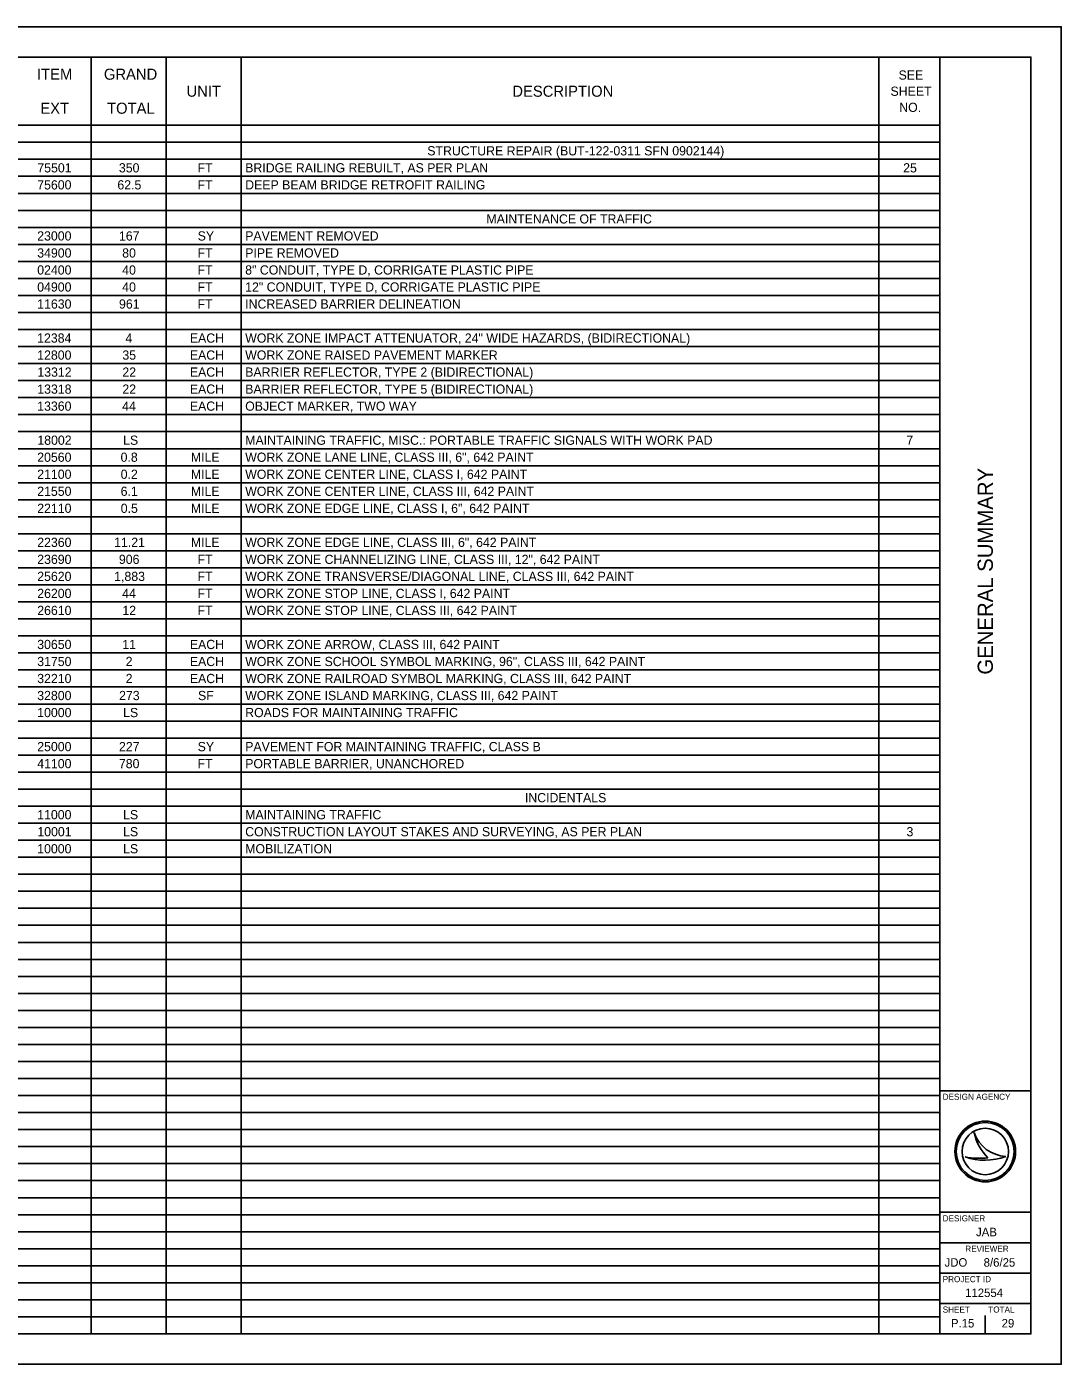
# Model space of a CAD drawing. Extents: x 45.7 to 120.9, y -0.1 to 21.9.
# Drawn here: x 103.83 to 120.86, y -0.09 to 21.91 of the extents above; entities that cross this region are included whole.
import ezdxf

# ---------------------------------------------------------------- set-up
doc = ezdxf.new("R2010")
doc.units = 0
for name, color, linetype in [('SH_Border', 7, 'Continuous'), ('SH_Cut_Line', 7, 'Continuous'), ('SH_Data', 7, 'Continuous'), ('SH_Text', 7, 'Continuous')]:
    doc.layers.add(name, color=color, linetype=linetype)

msp = doc.modelspace()

# ---------------------------------------------------------------- linework, layer by layer
at = {"layer": 'SH_Border'}
for p, q in [((118.856, 0.409), (118.856, 21.409)), ((118.856, 4.409), (120.356, 4.409)), ((118.856, 2.409), (120.356, 2.409)), ((118.856, 1.909), (120.356, 1.909)), ((118.856, 1.409), (120.356, 1.409)), ((118.856, 0.909), (120.356, 0.909))]:
    msp.add_line(p, q, dxfattribs=at)
msp.add_lwpolyline([(88.356, 21.409), (120.356, 21.409), (120.356, 0.409), (88.356, 0.409)], close=True, dxfattribs=at)
at = {"layer": 'SH_Cut_Line'}
msp.add_lwpolyline([(86.856, -0.091), (120.856, -0.091), (120.856, 21.909), (86.856, 21.909)], close=True, dxfattribs=at)
at = {"layer": 'SH_Data'}
for p, q in [((119.424, 3.719), (119.424, 3.719)), ((119.274, 3.319), (119.274, 3.319)), ((119.606, 3.409), (119.606, 3.409)), ((119.944, 3.328), (119.944, 3.328)), ((119.606, 0.409), (119.606, 0.709)), ((119.231, 0.584), (119.231, 0.584))]:
    msp.add_line(p, q, dxfattribs=at)
for radius in [0.5, 0.477, 0.477, 0.382]:
    msp.add_circle((119.606, 3.409), radius, dxfattribs=at)
for centre, radius, start, end in [((119.972, 3.907), 0.58, 198.9257, 198.9319), ((120.203, 3.879), 0.796, 191.6379, 191.6421), ((119.972, 3.907), 0.58, 198.9319, 267.1657), ((120.203, 3.879), 0.796, 191.6421, 226.0947), ((119.596, 4.279), 1.013, 251.4576, 290.0832), ((119.504, 4.563), 1.266, 259.4964, 259.4995), ((119.596, 4.279), 1.013, 251.4527, 251.4576), ((119.504, 4.563), 1.266, 259.4995, 276.6672)]:
    msp.add_arc(centre, radius, start, end, dxfattribs=at)
at = {"layer": 'SH_Text'}
for p, q in [((88.356, 21.409), (118.86, 21.409)), ((104.893, 21.409), (104.893, 0.409)), ((106.128, 21.409), (106.128, 0.409)), ((107.363, 21.409), (107.363, 0.409)), ((117.855, 21.409), (117.855, 0.409)), ((118.86, 21.409), (118.86, 0.409)), ((88.356, 20.289), (118.86, 20.289)), ((88.356, 20.009), (118.86, 20.009)), ((88.356, 19.729), (118.86, 19.729)), ((88.356, 19.449), (118.86, 19.449)), ((88.356, 19.169), (118.86, 19.169)), ((88.356, 18.889), (118.86, 18.889)), ((88.356, 18.609), (118.86, 18.609)), ((88.356, 18.329), (118.86, 18.329)), ((88.356, 18.049), (118.86, 18.049)), ((88.356, 17.769), (118.86, 17.769)), ((88.356, 17.489), (118.86, 17.489)), ((88.356, 17.209), (118.86, 17.209)), ((88.356, 16.929), (118.86, 16.929)), ((88.356, 16.649), (118.86, 16.649)), ((88.356, 16.369), (118.86, 16.369)), ((88.356, 16.089), (118.86, 16.089)), ((88.356, 15.809), (118.86, 15.809)), ((88.356, 15.529), (118.86, 15.529)), ((88.356, 15.249), (118.86, 15.249)), ((88.356, 14.969), (118.86, 14.969)), ((88.356, 14.689), (118.86, 14.689)), ((88.356, 14.409), (118.86, 14.409)), ((88.356, 14.129), (118.86, 14.129)), ((88.356, 13.849), (118.86, 13.849)), ((88.356, 13.569), (118.86, 13.569)), ((88.356, 13.289), (118.86, 13.289)), ((88.356, 13.009), (118.86, 13.009)), ((88.356, 12.729), (118.86, 12.729)), ((88.356, 12.449), (118.86, 12.449)), ((88.356, 12.169), (118.86, 12.169)), ((88.356, 11.889), (118.86, 11.889)), ((88.356, 11.609), (118.86, 11.609)), ((88.356, 11.329), (118.86, 11.329)), ((88.356, 11.049), (118.86, 11.049)), ((88.356, 10.769), (118.86, 10.769)), ((88.356, 10.489), (118.86, 10.489)), ((88.356, 10.209), (118.86, 10.209)), ((88.356, 9.929), (118.86, 9.929)), ((88.356, 9.649), (118.86, 9.649)), ((88.356, 9.369), (118.86, 9.369)), ((88.356, 9.089), (118.86, 9.089)), ((88.356, 8.809), (118.86, 8.809)), ((88.356, 8.529), (118.86, 8.529)), ((88.356, 8.249), (118.86, 8.249)), ((88.356, 7.969), (118.86, 7.969)), ((88.356, 7.689), (118.86, 7.689)), ((88.356, 7.409), (118.86, 7.409)), ((88.356, 7.129), (118.86, 7.129)), ((88.356, 6.849), (118.86, 6.849)), ((88.356, 6.569), (118.86, 6.569)), ((88.356, 6.289), (118.86, 6.289)), ((88.356, 6.009), (118.86, 6.009)), ((88.356, 5.729), (118.86, 5.729)), ((88.356, 5.449), (118.86, 5.449)), ((88.356, 5.169), (118.86, 5.169)), ((88.356, 4.889), (118.86, 4.889)), ((88.356, 4.609), (118.86, 4.609)), ((88.356, 4.329), (118.86, 4.329)), ((88.356, 4.049), (118.86, 4.049)), ((88.356, 3.769), (118.86, 3.769)), ((88.356, 3.489), (118.86, 3.489)), ((88.356, 3.209), (118.86, 3.209)), ((88.356, 2.929), (118.86, 2.929)), ((88.356, 2.649), (118.86, 2.649)), ((88.356, 2.369), (118.86, 2.369)), ((88.356, 2.089), (118.86, 2.089)), ((88.356, 1.809), (118.86, 1.809)), ((88.356, 1.529), (118.86, 1.529)), ((88.356, 1.249), (118.86, 1.249)), ((88.356, 0.969), (118.86, 0.969)), ((88.356, 0.689), (118.86, 0.689)), ((88.356, 0.409), (118.86, 0.409))]:
    msp.add_line(p, q, dxfattribs=at)

# ---------------------------------------------------------------- texts
at = {"layer": 'SH_Data'}
msp.add_text('GENERAL SUMMARY', height=0.25, rotation=90, dxfattribs=at).set_placement((119.731, 11.253))
for s, height, p in [('DESIGN AGENCY', 0.1, (118.906, 4.259)), ('DESIGNER', 0.1, (118.906, 2.259)), ('JAB', 0.14, (119.454, 2.014)), ('REVIEWER', 0.1, (119.278, 1.759)), ('JDO', 0.14, (118.936, 1.514)), ('8/6/25', 0.14, (119.579, 1.514)), ('PROJECT ID', 0.1, (118.906, 1.259)), ('112554', 0.14, (119.274, 1.014)), ('SHEET', 0.1, (118.906, 0.759)), ('TOTAL', 0.1, (119.656, 0.759)), ('P.15', 0.14, (119.041, 0.514)), ('29', 0.14, (119.875, 0.514))]:
    msp.add_text(s, height=height, dxfattribs=at).set_placement(p)
at = {"layer": 'SH_Text'}
for s, height, p in [('ITEM', 0.1818, (104.004, 21.038)), ('GRAND', 0.1818, (105.104, 21.038)), ('SEE ', 0.1515, (118.18, 21.039)), ('UNIT', 0.1818, (106.463, 20.758)), ('DESCRIPTION', 0.18184, (111.824, 20.758)), ('SHEET ', 0.1515, (118.047, 20.773)), ('EXT', 0.1818, (104.058, 20.478)), ('TOTAL', 0.1818, (105.156, 20.478)), ('NO.', 0.1515, (118.191, 20.508)), ('STRUCTURE REPAIR (BUT-122-0311 SFN 0902144)', 0.15153, (110.425, 19.793)), ('75501', 0.1515, (104.009, 19.513)), ('350', 0.1515, (105.351, 19.513)), ('FT', 0.1515, (106.645, 19.513)), ('BRIDGE RAILING REBUILT, AS PER PLAN', 0.15153, (107.429, 19.513)), ('25', 0.1515, (118.255, 19.513)), ('75600', 0.1515, (104.007, 19.233)), ('62.5', 0.1515, (105.326, 19.233)), ('FT', 0.1515, (106.645, 19.233)), ('DEEP BEAM BRIDGE RETROFIT RAILING', 0.15153, (107.429, 19.233)), ('MAINTENANCE OF TRAFFIC', 0.15153, (111.398, 18.673)), ('23000', 0.1515, (104.007, 18.393)), ('167', 0.1515, (105.352, 18.393)), ('SY', 0.1515, (106.647, 18.393)), ('PAVEMENT REMOVED', 0.15153, (107.429, 18.393)), ('34900', 0.1515, (104.007, 18.113)), ('80', 0.1515, (105.405, 18.113)), ('FT', 0.1515, (106.645, 18.113)), ('PIPE REMOVED', 0.15153, (107.429, 18.113)), ('02400', 0.1515, (104.007, 17.833)), ('40', 0.1515, (105.405, 17.833)), ('FT', 0.1515, (106.645, 17.833)), ('8" CONDUIT, TYPE D, CORRIGATE PLASTIC PIPE', 0.15153, (107.429, 17.833)), ('04900', 0.1515, (104.007, 17.553)), ('40', 0.1515, (105.405, 17.553)), ('FT', 0.1515, (106.645, 17.553)), ('12" CONDUIT, TYPE D, CORRIGATE PLASTIC PIPE', 0.15153, (107.429, 17.553)), ('11630', 0.1515, (104.007, 17.273)), ('961', 0.1515, (105.353, 17.273)), ('FT', 0.1515, (106.645, 17.273)), ('INCREASED BARRIER DELINEATION', 0.15153, (107.429, 17.273)), ('12384', 0.1515, (104.006, 16.713)), ('4', 0.152, (105.459, 16.713)), ('EACH', 0.1515, (106.518, 16.713)), ('WORK ZONE IMPACT ATTENUATOR, 24" WIDE HAZARDS, (BIDIRECTIONAL)', 0.15153, (107.429, 16.713)), ('12800', 0.1515, (104.007, 16.433)), ('35', 0.1515, (105.408, 16.433)), ('EACH', 0.1515, (106.518, 16.433)), ('WORK ZONE RAISED PAVEMENT MARKER', 0.15153, (107.429, 16.433)), ('13312', 0.1515, (104.009, 16.153)), ('22', 0.1515, (105.408, 16.153)), ('EACH', 0.1515, (106.518, 16.153)), ('BARRIER REFLECTOR, TYPE 2 (BIDIRECTIONAL)', 0.15153, (107.429, 16.153)), ('13318', 0.1515, (104.008, 15.873)), ('22', 0.1515, (105.408, 15.873)), ('EACH', 0.1515, (106.518, 15.873)), ('BARRIER REFLECTOR, TYPE 5 (BIDIRECTIONAL)', 0.15153, (107.429, 15.873)), ('13360', 0.1515, (104.007, 15.593)), ('44', 0.1515, (105.405, 15.593)), ('EACH', 0.1515, (106.518, 15.593)), ('OBJECT MARKER, TWO WAY', 0.15153, (107.429, 15.593)), ('18002', 0.1515, (104.009, 15.033)), ('LS', 0.1515, (105.42, 15.033)), ('MAINTAINING TRAFFIC, MISC.: PORTABLE TRAFFIC SIGNALS WITH WORK PAD', 0.15153, (107.429, 15.033)), ('7', 0.152, (118.308, 15.033)), ('20560', 0.1515, (104.007, 14.753)), ('0.8', 0.1515, (105.379, 14.753)), ('MILE', 0.1515, (106.535, 14.753)), ('WORK ZONE LANE LINE, CLASS III, 6", 642 PAINT', 0.15153, (107.429, 14.753)), ('21100', 0.1515, (104.007, 14.473)), ('0.2', 0.1515, (105.38, 14.473)), ('MILE', 0.1515, (106.535, 14.473)), ('WORK ZONE CENTER LINE, CLASS I, 642 PAINT', 0.15153, (107.429, 14.473)), ('21550', 0.1515, (104.007, 14.193)), ('6.1', 0.1515, (105.38, 14.193)), ('MILE', 0.1515, (106.535, 14.193)), ('WORK ZONE CENTER LINE, CLASS III, 642 PAINT', 0.15153, (107.429, 14.193)), ('22110', 0.1515, (104.007, 13.913)), ('0.5', 0.1515, (105.381, 13.913)), ('MILE', 0.1515, (106.535, 13.913)), ('WORK ZONE EDGE LINE, CLASS I, 6", 642 PAINT', 0.15153, (107.429, 13.913)), ('22360', 0.1515, (104.007, 13.353)), ('11.21', 0.1515, (105.272, 13.353)), ('MILE', 0.1515, (106.535, 13.353)), ('WORK ZONE EDGE LINE, CLASS III, 6", 642 PAINT', 0.15153, (107.429, 13.353)), ('23690', 0.1515, (104.007, 13.073)), ('906', 0.1515, (105.351, 13.073)), ('FT', 0.1515, (106.645, 13.073)), ('WORK ZONE CHANNELIZING LINE, CLASS III, 12", 642 PAINT', 0.15153, (107.429, 13.073)), ('25620', 0.1515, (104.007, 12.793)), ('1,883', 0.1515, (105.273, 12.793)), ('FT', 0.1515, (106.645, 12.793)), ('WORK ZONE TRANSVERSE/DIAGONAL LINE, CLASS III, 642 PAINT', 0.15153, (107.429, 12.793)), ('26200', 0.1515, (104.007, 12.513)), ('44', 0.1515, (105.405, 12.513)), ('FT', 0.1515, (106.645, 12.513)), ('WORK ZONE STOP LINE, CLASS I, 642 PAINT', 0.15153, (107.429, 12.513)), ('26610', 0.1515, (104.007, 12.233)), ('12', 0.1515, (105.408, 12.233)), ('FT', 0.1515, (106.645, 12.233)), ('WORK ZONE STOP LINE, CLASS III, 642 PAINT', 0.15153, (107.429, 12.233)), ('30650', 0.1515, (104.007, 11.673)), ('11', 0.1515, (105.407, 11.673)), ('EACH', 0.1515, (106.518, 11.673)), ('WORK ZONE ARROW, CLASS III, 642 PAINT', 0.15153, (107.429, 11.673)), ('31750', 0.1515, (104.007, 11.393)), ('2', 0.152, (105.462, 11.393)), ('EACH', 0.1515, (106.518, 11.393)), ('WORK ZONE SCHOOL SYMBOL MARKING, 96", CLASS III, 642 PAINT', 0.15153, (107.429, 11.393)), ('32210', 0.1515, (104.007, 11.113)), ('2', 0.152, (105.462, 11.113)), ('EACH', 0.1515, (106.518, 11.113)), ('WORK ZONE RAILROAD SYMBOL MARKING, CLASS III, 642 PAINT', 0.15153, (107.429, 11.113)), ('32800', 0.1515, (104.007, 10.833)), ('273', 0.1515, (105.354, 10.833)), ('SF', 0.1515, (106.652, 10.833)), ('WORK ZONE ISLAND MARKING, CLASS III, 642 PAINT', 0.15153, (107.429, 10.833)), ('10000', 0.1515, (104.007, 10.553)), ('LS', 0.1515, (105.42, 10.553)), ('ROADS FOR MAINTAINING TRAFFIC', 0.15153, (107.429, 10.553)), ('25000', 0.1515, (104.007, 9.993)), ('227', 0.1515, (105.352, 9.993)), ('SY', 0.1515, (106.647, 9.993)), ('PAVEMENT FOR MAINTAINING TRAFFIC, CLASS B', 0.15153, (107.429, 9.993)), ('41100', 0.1515, (104.007, 9.713)), ('780', 0.1515, (105.351, 9.713)), ('FT', 0.1515, (106.645, 9.713)), ('PORTABLE BARRIER, UNANCHORED', 0.15153, (107.429, 9.713)), ('INCIDENTALS', 0.15153, (112.031, 9.153)), ('11000', 0.1515, (104.007, 8.873)), ('LS', 0.1515, (105.42, 8.873)), ('MAINTAINING TRAFFIC', 0.15153, (107.429, 8.873)), ('10001', 0.1515, (104.009, 8.593)), ('LS', 0.1515, (105.42, 8.593)), ('CONSTRUCTION LAYOUT STAKES AND SURVEYING, AS PER PLAN', 0.15153, (107.429, 8.593)), ('3', 0.152, (118.31, 8.593)), ('10000', 0.1515, (104.007, 8.313)), ('LS', 0.1515, (105.42, 8.313)), ('MOBILIZATION', 0.15153, (107.429, 8.313))]:
    msp.add_text(s, height=height, dxfattribs=at).set_placement(p)

doc.saveas('drawing.dxf')
